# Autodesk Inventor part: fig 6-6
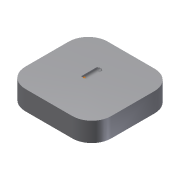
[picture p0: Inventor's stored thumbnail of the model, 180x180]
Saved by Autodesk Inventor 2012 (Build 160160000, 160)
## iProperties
Created: 2004-05
Part Number: fig 6-6
Document SubType Name: Modeling
Designer: CADCIM Technologies
Manufacturer: Standard
Standards Organization: Custom
Density: 1 g/cm^3
Material: Default
Author: CADCIM Technologies
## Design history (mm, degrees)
sketch "Sketch1"
  geometry: L1 (0, 0)-(44.293, 0); L2 (44.293, 0)-(44.293, 42.442); L3 (44.293, 42.442)-(0, 42.442); L4 (0, 42.442)-(0, 0)
  constraints: 8 end point, 2 parallel, 1 horizontal, 1 perpendicular
extrude "Extrusion1" new body sketch "Sketch1" distance "d0" = 10; taper "d1" = 0 deg
fillet "Fillet1" dims "d2" = 10
sketch "Sketch2"
  geometry: 1 further point
sketch "Sketch3"
  geometry: L1 (10, 42.442)-(34.293, 42.442) reference; L2 (0, 10)-(0, 32.442) reference; L3 (34.293, 0)-(10, 0) reference; L4 (44.293, 32.442)-(44.293, 10) reference; A1 r 10 centre (34.293, 32.442) between (44.293, 32.442) and (34.293, 42.442) reference; A2 r 10 centre (10, 32.442) between (10, 42.442) and (0, 32.442) reference; A3 r 10 centre (10, 10) between (0, 10) and (10, 0) reference; A4 r 10 centre (34.293, 10) between (34.293, 0) and (44.293, 10) reference; 1 further point
workpoint "Work Point1"
hole "Hole4" diameter "d33" = 3; stored, may be unused: countersink angle "d37" = 90 deg, drill point angle "d39" = 118 deg; dims "d31" = 10, "d32" = 10, "d34" = 6, "d35" = 4, "d36" = 2, "d38" = 8
body "Solid1"
